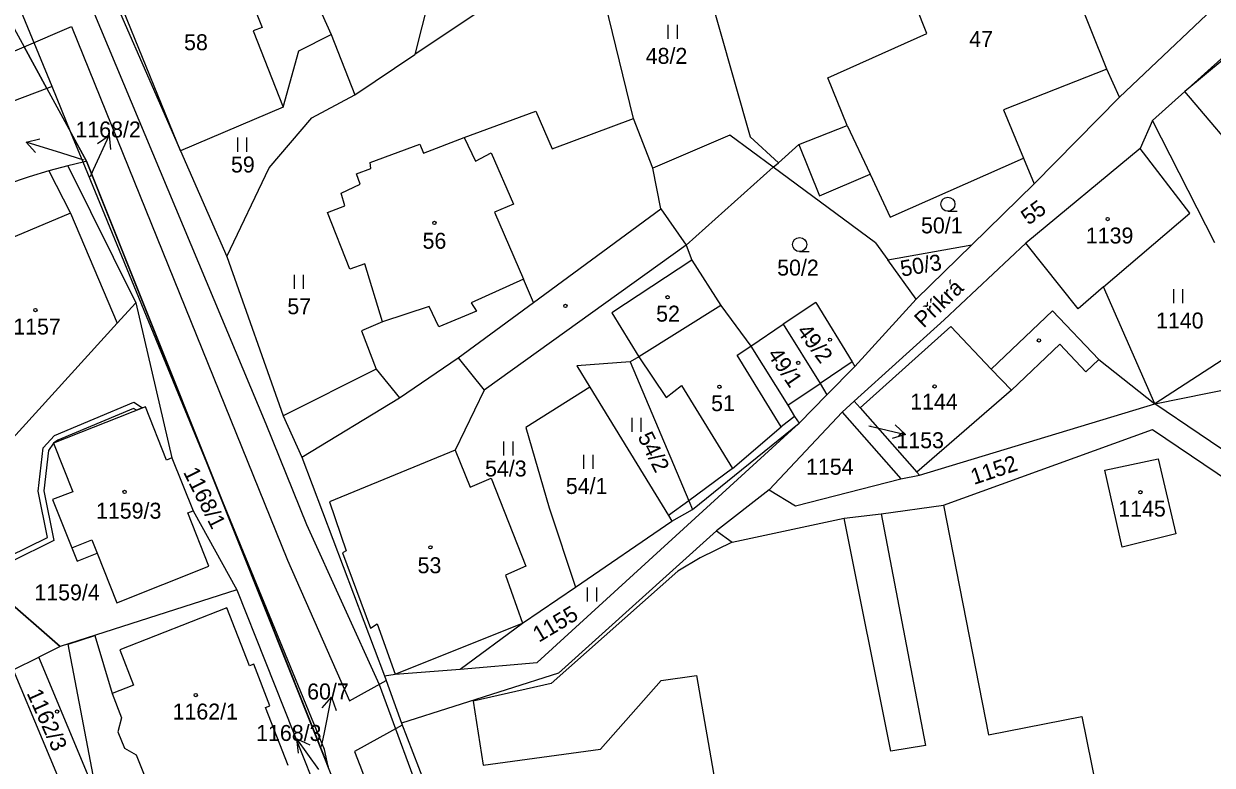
# Model space of a CAD drawing. Extents: x -670359 to -660124, y -978807 to -970072.
# Drawn here: x -670231.4 to -670104.9, y -977870.8 to -977791.9 of the extents above; entities that cross this region are included whole.
import ezdxf

# ---------------------------------------------------------------- set-up
doc = ezdxf.new("R2010")
doc.units = 0
for name, color, linetype in [('Hranice parcel', 7, 'Continuous'), ('Parcelní čísla', 7, 'Continuous'), ('Pop  PČ popisy', 7, 'Continuous'), ('Vnitřní kresba', 7, 'Continuous'), ('Věcná břemena k části', 7, 'Continuous'), ('Značky budov', 7, 'Continuous'), ('Značky kultur', 7, 'Continuous')]:
    doc.layers.add(name, color=color, linetype=linetype)

msp = doc.modelspace()

# ---------------------------------------------------------------- linework, layer by layer
at = {"layer": 'Hranice parcel'}
for points in [[(-670228.39, -977798.54), (-670235.68, -977780.88), (-670248.21, -977752.09), (-670257.66, -977728.06), (-670261.88, -977714.27), (-670262.87, -977707.81), (-670263.3, -977700.83), (-670262.9, -977694.87), (-670261.36, -977686.41), (-670250.36, -977641.2)], [(-670183.39, -977889.81), (-670193.56, -977862.25), (-670201.26, -977845.22), (-670205.62, -977834.5), (-670231.98, -977771.32), (-670242.71, -977745.05), (-670249.53, -977728.04), (-670253.85, -977714.41), (-670254.54, -977710.9), (-670255.07, -977705.75), (-670255.17, -977699.87), (-670254.7, -977694.67), (-670252.82, -977684.15), (-670242.83, -977643.13)], [(-670170.72, -977719.8), (-670189.77, -977795.14)], [(-670116.13, -977796.71), (-670126.35, -977771.21)], [(-670241.06, -977776.57), (-670231.37, -977794.32), (-670228.95, -977798.75), (-670226.38, -977803.45)], [(-670135.31, -977792.9), (-670141.44, -977777.42)], [(-670160.77, -977780.44), (-670154.08, -977803.89)], [(-670224.46, -977783.08), (-670214.71, -977805.39)], [(-670171.73, -977783.05), (-670189.77, -977795.14)], [(-670089.7, -977782.74), (-670107.82, -977799.09)], [(-670166.5, -977801.96), (-670170.62, -977785.06)], [(-670201.68, -977786.36), (-670198.69, -977793.02)], [(-670093.41, -977787.03), (-670107.82, -977799.09)], [(-670114.79, -977799.68), (-670102.21, -977787.73)], [(-670202.14, -977794.75), (-670198.69, -977793.02)], [(-670198.69, -977793.02), (-670196.17, -977799.43)], [(-670145.82, -977797.63), (-670135.31, -977792.9)], [(-670203.78, -977800.74), (-670202.14, -977794.75)], [(-670196.17, -977799.43), (-670189.77, -977795.14)], [(-670114.79, -977799.68), (-670116.13, -977796.71)], [(-670143.78, -977802.68), (-670145.82, -977797.63)], [(-670226.38, -977803.45), (-670228.39, -977798.54)], [(-670200.75, -977801.88), (-670196.17, -977799.43)], [(-670123.86, -977808.92), (-670114.79, -977799.68)], [(-670107.82, -977799.09), (-670111.29, -977802.18)], [(-670203.78, -977800.74), (-670214.71, -977805.39)], [(-670205.27, -977807.21), (-670200.75, -977801.88)], [(-670184.52, -977803.99), (-670176.9, -977801.17)], [(-670176.9, -977801.17), (-670175.17, -977805.18)], [(-670175.17, -977805.18), (-670166.5, -977801.96)], [(-670164.46, -977807.25), (-670166.5, -977801.96)], [(-670111.29, -977802.18), (-670112.59, -977805.14)], [(-670104.66, -977815.19), (-670111.29, -977802.18)], [(-670226.38, -977803.45), (-670224.71, -977806.51)], [(-670225.09, -977806.6), (-670226.38, -977803.45)], [(-670148.92, -977804.72), (-670143.78, -977802.68)], [(-670194.54, -977806.64), (-670189.25, -977804.68)], [(-670189.25, -977804.68), (-670188.86, -977805.64)], [(-670188.86, -977805.64), (-670184.52, -977803.99)], [(-670154.08, -977803.89), (-670151.09, -977806.66)], [(-670148.92, -977804.72), (-670151.09, -977806.66)], [(-670148.92, -977804.72), (-670146.72, -977810.18)], [(-670214.71, -977805.39), (-670209.78, -977816.65)], [(-670112.59, -977805.14), (-670124.75, -977815.21)], [(-670107.3, -977812.02), (-670112.59, -977805.14)], [(-670226.72, -977806.98), (-670228.72, -977807.52)], [(-670225.09, -977806.6), (-670226.72, -977806.98)], [(-670226.72, -977806.98), (-670219.46, -977821.58)], [(-670224.71, -977806.51), (-670225.09, -977806.6)], [(-670211.12, -977840.59), (-670225.09, -977806.6)], [(-670224.71, -977806.51), (-670211.12, -977840.59)], [(-670209.78, -977816.65), (-670205.27, -977807.21)], [(-670195.99, -977807.83), (-670194.47, -977807.28)], [(-670194.47, -977807.28), (-670194.54, -977806.64)], [(-670163.61, -977811.58), (-670164.46, -977807.25)], [(-670160.92, -977815.43), (-670151.63, -977807.14)], [(-670151.63, -977807.14), (-670151.09, -977806.66)], [(-670140.75, -977815.18), (-670151.63, -977807.14)], [(-670139.21, -977812.47), (-670125, -977806.17)], [(-670125, -977806.17), (-670123.86, -977808.92)], [(-670230.81, -977808.15), (-670240.51, -977811.44)], [(-670228.72, -977807.52), (-670230.81, -977808.15)], [(-670228.72, -977807.52), (-670226.43, -977812.02)], [(-670195.6, -977808.95), (-670195.99, -977807.83)], [(-670146.72, -977810.18), (-670141.34, -977807.89)], [(-670141.34, -977807.89), (-670139.21, -977812.47)], [(-670197.61, -977809.9), (-670195.6, -977808.95)], [(-670123.86, -977808.92), (-670130.5, -977815.4)], [(-670197.22, -977811.26), (-670197.61, -977809.9)], [(-670226.43, -977812.02), (-670240, -977817.76)], [(-670199.06, -977811.97), (-670197.22, -977811.26)], [(-670196.71, -977817.98), (-670199.06, -977811.97)], [(-670177.17, -977821.54), (-670163.61, -977811.58)], [(-670163.61, -977811.58), (-670160.92, -977815.43)], [(-670116.48, -977819.88), (-670107.3, -977812.02)], [(-670160.92, -977815.43), (-670182.39, -977830.88)], [(-670160.92, -977815.43), (-670160.29, -977817.04)], [(-670140.75, -977815.18), (-670139.43, -977817.01)], [(-670139.43, -977817.01), (-670130.5, -977815.4)], [(-670136.43, -977821.2), (-670130.5, -977815.4)], [(-670124.75, -977815.21), (-670133.45, -977823.38)], [(-670119.19, -977822.2), (-670124.75, -977815.21)], [(-670209.78, -977816.65), (-670203.78, -977833.61)], [(-670195.1, -977817.44), (-670196.71, -977817.98)], [(-670193.23, -977823.61), (-670195.1, -977817.44)], [(-670160.29, -977817.04), (-670168.81, -977822.66)], [(-670160.29, -977817.04), (-670157.2, -977821.86)], [(-670136.43, -977821.2), (-670139.43, -977817.01)], [(-670178.23, -977819.07), (-670183.77, -977821.59)], [(-670177.17, -977821.54), (-670178.23, -977819.07)], [(-670116.48, -977819.88), (-670119.19, -977822.2)], [(-670111.02, -977832.34), (-670116.48, -977819.88)], [(-670142.95, -977828.35), (-670136.43, -977821.2)], [(-670219.46, -977821.58), (-670221.47, -977823.73)], [(-670219.46, -977821.58), (-670215.65, -977838.09)], [(-670188.25, -977821.96), (-670193.23, -977823.61)], [(-670187.23, -977824.13), (-670188.25, -977821.96)], [(-670183.21, -977822.48), (-670187.23, -977824.13)], [(-670185.17, -977827.42), (-670177.17, -977821.54)], [(-670183.77, -977821.59), (-670183.21, -977822.48)], [(-670157.2, -977821.86), (-670165.96, -977827.32)], [(-670157.2, -977821.86), (-670154.03, -977826.2)], [(-670147.12, -977821.53), (-670150.58, -977823.86)], [(-670147.12, -977821.53), (-670143.24, -977827.87)], [(-670221.47, -977823.73), (-670235.03, -977838.67)], [(-670168.81, -977822.66), (-670165.96, -977827.32)], [(-670133.45, -977823.38), (-670143.02, -977832.05)], [(-670154.03, -977826.2), (-670150.58, -977823.86)], [(-670150.58, -977823.86), (-670146.66, -977830.17)], [(-670154.03, -977826.2), (-670150.08, -977832.47)], [(-670099.93, -977825.14), (-670111.02, -977832.34)], [(-670191.4, -977831.7), (-670185.17, -977827.42)], [(-670165.96, -977827.32), (-670166.85, -977827.87)], [(-670166.85, -977827.87), (-670172.55, -977828.3)], [(-670172.55, -977828.3), (-670171.16, -977830.57)], [(-670166.85, -977827.87), (-670160.63, -977842.65)], [(-670142.95, -977828.35), (-670145.92, -977831.37)], [(-670143.24, -977827.87), (-670142.95, -977828.35)], [(-670111.02, -977832.34), (-670099.64, -977830.02)], [(-670182.39, -977830.88), (-670185.48, -977837.26)], [(-670171.16, -977830.57), (-670177.98, -977834.86)], [(-670171.16, -977830.57), (-670162.79, -977844.24)], [(-670146.66, -977830.17), (-670145.92, -977831.37)], [(-670201.81, -977838.02), (-670191.4, -977831.7)], [(-670150.08, -977832.47), (-670149.36, -977833.67)], [(-670148.89, -977834.39), (-670145.92, -977831.37)], [(-670143.02, -977832.05), (-670144.32, -977833.23)], [(-670143.02, -977832.05), (-670142.4, -977832.76)], [(-670136.08, -977839.92), (-670111.02, -977832.34)], [(-670087.45, -977848.3), (-670111.02, -977832.34)], [(-670218.46, -977832.65), (-670228.24, -977836.52)], [(-670216.21, -977838.32), (-670218.46, -977832.65)], [(-670203.78, -977833.61), (-670201.81, -977838.02)], [(-670144.32, -977833.23), (-670152.06, -977841.49)], [(-670149.36, -977833.67), (-670148.89, -977834.39)], [(-670144.32, -977833.23), (-670138.05, -977840.31)], [(-670142.4, -977832.76), (-670136.36, -977839.6)], [(-670177.98, -977834.86), (-670175.47, -977843.4), (-670172.69, -977851.85)], [(-670176.76, -977859.87), (-670148.89, -977834.39)], [(-670160.24, -977843.59), (-670148.89, -977834.39)], [(-670133.51, -977843.14), (-670111.28, -977835.06)], [(-670111.28, -977835.06), (-670086.58, -977851.74)], [(-670228.24, -977836.52), (-670226.19, -977841.7)], [(-670185.48, -977837.26), (-670183.91, -977841.19)], [(-670215.65, -977838.09), (-670216.21, -977838.32)], [(-670215.65, -977838.09), (-670213.37, -977843.72)], [(-670201.81, -977838.02), (-670193.02, -977861.28)], [(-670116.35, -977839.38), (-670110.67, -977838.18)], [(-670110.67, -977838.18), (-670108.8, -977846.19)], [(-670138.05, -977840.31), (-670136.08, -977839.92)], [(-670136.36, -977839.6), (-670136.08, -977839.92)], [(-670114.49, -977847.59), (-670116.35, -977839.38)], [(-670199.01, -977870.96), (-670199.39, -977869.14), (-670211.12, -977840.59)], [(-670211.12, -977840.59), (-670199.01, -977870.96)], [(-670183.91, -977841.19), (-670181.66, -977840.24)], [(-670181.66, -977840.24), (-670177.97, -977849.63)], [(-670149.27, -977843.19), (-670138.05, -977840.31)], [(-670226.19, -977841.7), (-670228.33, -977842.51)], [(-670228.33, -977842.51), (-670226.3, -977847.66)], [(-670160.63, -977842.65), (-670160.24, -977843.59)], [(-670152.06, -977841.49), (-670157.69, -977845.85)], [(-670152.06, -977841.49), (-670149.27, -977843.19)], [(-670213.94, -977843.94), (-670213.37, -977843.72)], [(-670211.69, -977849.63), (-670213.94, -977843.94)], [(-670213.37, -977843.72), (-670208.71, -977852.13)], [(-670162.42, -977844.84), (-670160.24, -977843.59)], [(-670140.16, -977844.05), (-670133.51, -977843.14)], [(-670133.51, -977843.14), (-670128.72, -977867.57)], [(-670172.69, -977851.85), (-670162.42, -977844.84)], [(-670162.79, -977844.24), (-670162.42, -977844.84)], [(-670156.02, -977847.06), (-670144.08, -977844.5)], [(-670144.08, -977844.5), (-670140.16, -977844.05)], [(-670157.69, -977845.85), (-670174.49, -977861)], [(-670157.69, -977845.85), (-670156.02, -977847.06)], [(-670108.8, -977846.19), (-670114.49, -977847.59)], [(-670226.3, -977847.66), (-670225.73, -977849.08)], [(-670225.73, -977849.08), (-670223.6, -977848.23)], [(-670223.6, -977848.23), (-670221.5, -977853.52)], [(-670221.5, -977853.52), (-670211.69, -977849.63)], [(-670177.97, -977849.63), (-670180.14, -977850.57)], [(-670180.14, -977850.57), (-670178.33, -977855.7)], [(-670234.05, -977852.48), (-670227.51, -977858.17)], [(-670208.71, -977852.13), (-670227.51, -977858.17)], [(-670208.71, -977852.13), (-670199.68, -977874.91)], [(-670178.33, -977855.7), (-670172.69, -977851.85)], [(-670209.8, -977854.06), (-670221.19, -977858.51)], [(-670207.39, -977860.24), (-670209.8, -977854.06)], [(-670184.95, -977860.58), (-670178.33, -977855.7)], [(-670227.51, -977858.17), (-670229.81, -977859.3)], [(-670221.19, -977858.51), (-670219.71, -977862.3)], [(-670232.52, -977860.64), (-670229.81, -977859.3)], [(-670223.55, -977874.27), (-670229.81, -977859.3)], [(-670206.92, -977860.06), (-670207.39, -977860.24)], [(-670205.23, -977864.49), (-670206.92, -977860.06)], [(-670184.95, -977860.58), (-670176.76, -977859.87)], [(-670232.52, -977860.64), (-670226.34, -977875.43)], [(-670193.02, -977861.28), (-670191.89, -977861.13)], [(-670193.02, -977861.28), (-670191.21, -977866.33)], [(-670191.89, -977861.13), (-670184.95, -977860.58)], [(-670174.49, -977861), (-670191.21, -977866.33)], [(-670219.71, -977862.3), (-670221.99, -977863.19)], [(-670221.99, -977863.19), (-670220.99, -977865.75)], [(-670205.66, -977864.66), (-670205.23, -977864.49)], [(-670203.25, -977870.84), (-670205.66, -977864.66)], [(-670220.99, -977865.75), (-670221.4, -977867.26)], [(-670191.21, -977866.33), (-670188.19, -977874.13)], [(-670128.72, -977867.57), (-670118.79, -977865.64)], [(-670118.79, -977865.64), (-670116.23, -977878.21)], [(-670221.4, -977867.26), (-670220.69, -977869.01)], [(-670220.69, -977869.01), (-670219.45, -977869.7)], [(-670219.45, -977869.7), (-670218.37, -977872.37)]]:
    msp.add_lwpolyline(points, dxfattribs=at)
at = {"layer": 'Parcelní čísla'}
for p, q in [((-670230.14, -977805.56), (-670231.16, -977804.46)), ((-670223.54, -977804.62), (-670222.32, -977803.75)), ((-670225, -977806.38), (-670227.34, -977805.65)), ((-670224.31, -977808.13), (-670223.97, -977807.39)), ((-670138.65, -977834.56), (-670137.56, -977835.6)), ((-670199.64, -977864.7), (-670198.65, -977863.57)), ((-670202.18, -977869.52), (-670202.34, -977868.02)), ((-670199.7, -977868.81), (-670199.43, -977867.49))]:
    msp.add_line(p, q, dxfattribs=at)
for points in [[(-670227.34, -977805.65), (-670231.16, -977804.46), (-670229.7, -977804.13)], [(-670223.97, -977807.39), (-670222.32, -977803.75), (-670222.17, -977805.24)], [(-670141.45, -977834.66), (-670137.56, -977835.6), (-670139, -977836.02)], [(-670199.43, -977867.49), (-670198.65, -977863.57), (-670198.17, -977864.99)], [(-670199.99, -977871.26), (-670202.34, -977868.02), (-670200.97, -977868.64)]]:
    msp.add_lwpolyline(points, dxfattribs=at)
at = {"layer": 'Vnitřní kresba'}
for points in [[(-670214.71, -977805.39), (-670222.8, -977785.49)], [(-670207.93, -977787.43), (-670206.04, -977792.25)], [(-670206.04, -977792.25), (-670206.98, -977792.62)], [(-670206.98, -977792.62), (-670203.78, -977800.74)], [(-670116.13, -977796.71), (-670127.12, -977801.03)], [(-670100.84, -977807.3), (-670107.82, -977799.09)], [(-670127.12, -977801.03), (-670125, -977806.17)], [(-670143.78, -977802.68), (-670141.34, -977807.89)], [(-670184.52, -977803.99), (-670183.34, -977806.48)], [(-670156.27, -977803.71), (-670164.46, -977807.25)], [(-670151.63, -977807.14), (-670156.27, -977803.71)], [(-670183.34, -977806.48), (-670181.65, -977805.61)], [(-670181.65, -977805.61), (-670179.29, -977811.07)], [(-670179.29, -977811.07), (-670181.3, -977811.93)], [(-670226.43, -977812.02), (-670221.47, -977823.73)], [(-670181.3, -977811.93), (-670178.23, -977819.07)], [(-670128.43, -977828.63), (-670121.91, -977822.42)], [(-670121.91, -977822.42), (-670116.98, -977827.6)], [(-670193.23, -977823.61), (-670195.47, -977824.55)], [(-670195.47, -977824.55), (-670193.9, -977828.64)], [(-670142.4, -977832.76), (-670132.73, -977824.11)], [(-670132.73, -977824.11), (-670128.43, -977828.63)], [(-670155.48, -977827.15), (-670154.03, -977826.2)], [(-670121.15, -977825.97), (-670126.3, -977830.87)], [(-670118.36, -977828.91), (-670121.15, -977825.97)], [(-670185.17, -977827.42), (-670182.39, -977830.88)], [(-670165.96, -977827.32), (-670163.03, -977831.66)], [(-670150.81, -977834.78), (-670155.48, -977827.15)], [(-670193.9, -977828.64), (-670203.78, -977833.61)], [(-670193.9, -977828.64), (-670191.4, -977831.7)], [(-670143.24, -977827.87), (-670146.66, -977830.17)], [(-670128.43, -977828.63), (-670126.3, -977830.87)], [(-670116.98, -977827.6), (-670118.36, -977828.91)], [(-670116.98, -977827.6), (-670111.02, -977832.34)], [(-670163.03, -977831.66), (-670161.42, -977830.39)], [(-670161.42, -977830.39), (-670155.97, -977839.22)], [(-670150.08, -977832.47), (-670146.66, -977830.17)], [(-670126.3, -977830.87), (-670136.36, -977839.6)], [(-670149.36, -977833.67), (-670150.81, -977834.78)], [(-670155.97, -977839.22), (-670150.81, -977834.78)], [(-670185.48, -977837.26), (-670198.88, -977842.76)], [(-670155.97, -977839.22), (-670160.63, -977842.65)], [(-670160.63, -977842.65), (-670162.79, -977844.24)], [(-670198.88, -977842.76), (-670197.08, -977847.97)], [(-670139.14, -977869.33), (-670144.08, -977844.5)], [(-670140.16, -977844.05), (-670135.45, -977868.72)], [(-670226.3, -977847.66), (-670224.16, -977846.81)], [(-670224.16, -977846.81), (-670223.6, -977848.23)], [(-670156.02, -977847.06), (-670159.4, -977848.72)], [(-670197.08, -977847.97), (-670197.48, -977848.21)], [(-670197.48, -977848.21), (-670194.5, -977856.23)], [(-670159.4, -977848.72), (-670161.81, -977850.14)], [(-670161.81, -977850.14), (-670175.26, -977862.12)], [(-670194.5, -977856.23), (-670193.78, -977855.75)], [(-670193.78, -977855.75), (-670191.89, -977861.13)], [(-670191.89, -977861.13), (-670178.33, -977855.7)], [(-670163.57, -977861.8), (-670159.81, -977861.27)], [(-670159.81, -977861.27), (-670157.73, -977873.28)], [(-670175.26, -977862.12), (-670183.59, -977863.98)], [(-670170.03, -977869.12), (-670163.57, -977861.8)], [(-670183.59, -977863.98), (-670182.52, -977870.79)], [(-670182.52, -977870.79), (-670170.03, -977869.12)], [(-670135.45, -977868.72), (-670139.14, -977869.33)]]:
    msp.add_lwpolyline(points, dxfattribs=at)
at = {"layer": 'Věcná břemena k části'}
for points in [[(-670231.37, -977794.32), (-670226.31, -977792.17), (-670203.33, -977848.99), (-670196.72, -977863.94), (-670192.84, -977861.8), (-670191.21, -977866.33), (-670191.12, -977866.56), (-670196.22, -977869.36), (-670195.63, -977870.79), (-670152.49, -977985.64), (-670151.43, -977993.09), (-670152.31, -978015.47), (-670159.21, -978043.03)], [(-670257.67, -977808.33), (-670256.79, -977805.13), (-670231.37, -977794.32)], [(-670231.37, -977794.32), (-670228.95, -977798.75), (-670250.62, -977806.97)], [(-670228.39, -977798.54), (-670228.95, -977798.75), (-670231.37, -977794.32)], [(-670226.38, -977803.45), (-670228.39, -977798.54)], [(-670159.21, -978043.03), (-670166.44, -978073.84), (-670169.93, -978096.39), (-670171.6, -978117.05), (-670173.62, -978117.69), (-670174.87, -978118.08), (-670174.67, -978116.45), (-670172.91, -978096.03), (-670169.38, -978073.26), (-670162.13, -978042.33), (-670155.29, -978015.05), (-670154.43, -977993.25), (-670155.41, -977986.38), (-670176.81, -977929.42), (-670177.71, -977925.53), (-670186.89, -977901.98), (-670197.75, -977874.12), (-670224.71, -977806.51), (-670226.38, -977803.45)], [(-670235.03, -977838.67), (-670221.47, -977823.73), (-670219.46, -977821.58), (-670215.65, -977838.09), (-670216.21, -977838.32), (-670218.46, -977832.65), (-670228.24, -977836.52), (-670226.19, -977841.7), (-670228.33, -977842.51), (-670226.3, -977847.66), (-670225.73, -977849.08), (-670223.6, -977848.23), (-670221.5, -977853.52), (-670211.69, -977849.63), (-670213.94, -977843.94), (-670213.37, -977843.72), (-670208.71, -977852.13), (-670227.51, -977858.17), (-670234.05, -977852.48)], [(-670233, -977848.58), (-670228.87, -977846.55), (-670229.87, -977841.62), (-670229.33, -977837.03), (-670228.12, -977835.71), (-670219.67, -977832.15), (-670218.76, -977832.77)], [(-670218.76, -977832.77), (-670219.39, -977833.02), (-670219.74, -977832.83), (-670227.77, -977836.21), (-670228.24, -977836.52), (-670228.76, -977837.29), (-670229.26, -977841.59), (-670228.19, -977846.88), (-670232.77, -977849.14)], [(-670226.69, -977857.91), (-670223.83, -977856.99), (-670221.99, -977863.19), (-670220.99, -977865.75), (-670221.4, -977867.26), (-670220.69, -977869.01), (-670219.45, -977869.7), (-670218.37, -977872.37), (-670219.76, -977872.93), (-670218.52, -977879.98), (-670219.34, -977884.64), (-670222.56, -977885.63), (-670221.48, -977879.46), (-670223.55, -977874.27), (-670226.69, -977857.91)]]:
    msp.add_lwpolyline(points, dxfattribs=at)
at = {"layer": 'Značky budov'}
for centre in [(-670187.7, -977813.07), (-670116.05, -977812.66), (-670162.89, -977820.98), (-670230.16, -977822.35), (-670145.6, -977825.5), (-670148.98, -977827.97), (-670157.36, -977830.51), (-670134.47, -977830.48), (-670220.67, -977841.71), (-670112.56, -977841.74), (-670188.12, -977847.61), (-670213.09, -977863.34), (-670227.86, -977865.1)]:
    msp.add_circle(centre, 0.175, dxfattribs=at)
at = {"layer": 'Značky kultur'}
for p, q in [((-670162.84, -977791.96), (-670162.84, -977793.46)), ((-670161.84, -977793.46), (-670161.84, -977791.96)), ((-670208.67, -977803.99), (-670208.67, -977805.49)), ((-670207.67, -977805.49), (-670207.67, -977803.99)), ((-670133.05, -977811.83), (-670132.05, -977811.83)), ((-670148.83, -977816.12), (-670147.83, -977816.12)), ((-670202.64, -977818.59), (-670202.64, -977820.09)), ((-670201.64, -977820.09), (-670201.64, -977818.59)), ((-670109.04, -977820.11), (-670109.04, -977821.61)), ((-670108.04, -977821.61), (-670108.04, -977820.11)), ((-670166.7, -977833.81), (-670166.7, -977835.31)), ((-670165.7, -977835.31), (-670165.7, -977833.81)), ((-670180.33, -977836.34), (-670180.33, -977837.84)), ((-670179.33, -977837.84), (-670179.33, -977836.34)), ((-670171.82, -977837.77), (-670171.82, -977839.27)), ((-670170.82, -977839.27), (-670170.82, -977837.77)), ((-670171.43, -977851.88), (-670171.43, -977853.38)), ((-670170.43, -977853.38), (-670170.43, -977851.88))]:
    msp.add_line(p, q, dxfattribs=at)
for centre, radius in [((-670133.05, -977811.08), 0.75), ((-670187.7, -977813.07), 0.175), ((-670116.05, -977812.66), 0.175), ((-670148.83, -977815.37), 0.75), ((-670162.89, -977820.98), 0.175), ((-670230.16, -977822.35), 0.175), ((-670173.75, -977821.91), 0.175), ((-670145.6, -977825.5), 0.175), ((-670123.37, -977825.58), 0.175), ((-670148.98, -977827.97), 0.175), ((-670157.36, -977830.51), 0.175), ((-670134.47, -977830.48), 0.175), ((-670220.67, -977841.71), 0.175), ((-670112.56, -977841.74), 0.175), ((-670188.12, -977847.61), 0.175), ((-670213.09, -977863.34), 0.175), ((-670227.86, -977865.1), 0.175)]:
    msp.add_circle(centre, radius, dxfattribs=at)

# ---------------------------------------------------------------- texts
at = {"layer": 'Parcelní čísla'}
for s, height, p in [('58', 1.7, (-670214.34, -977794.68)), ('47', 1.7, (-670130.78, -977794.33)), ('48/2', 1.7, (-670165.21, -977796.13)), ('1168/2', 1.7, (-670225.9, -977803.97)), ('59', 1.7, (-670209.35, -977807.7)), ('61/6', 0.1, (-670225.15, -977806.38)), ('1168/2', 0.1, (-670224.54, -977808.13)), ('50/1', 1.7, (-670135.91, -977814.18)), ('1139', 1.7, (-670118.37, -977815.26)), ('56', 1.7, (-670188.96, -977815.82)), ('50/2', 1.7, (-670151.22, -977818.68)), ('57', 1.7, (-670203.35, -977822.79)), ('52', 1.7, (-670164.1, -977823.58)), ('1157', 1.7, (-670232.52, -977824.95)), ('1140', 1.7, (-670110.9, -977824.31)), ('1144', 1.7, (-670137.06, -977832.94)), ('51', 1.7, (-670158.25, -977833.11)), ('1153', 0.1, (-670141.45, -977834.66)), ('1153', 1.7, (-670138.53, -977837.06)), ('54/3', 1.7, (-670182.31, -977840.07)), ('1154', 1.7, (-670148.15, -977839.88)), ('54/1', 1.7, (-670173.71, -977841.93)), ('1145', 1.7, (-670114.92, -977844.34)), ('1159/3', 1.7, (-670223.71, -977844.56)), ('53', 1.7, (-670189.49, -977850.37)), ('1159/4', 1.7, (-670230.27, -977853.26)), ('60/7', 1.7, (-670201.24, -977863.81)), ('1162/1', 1.7, (-670215.56, -977865.95)), ('1168/3', 1.7, (-670206.67, -977868.23)), ('60/7', 0.1, (-670199.86, -977868.81))]:
    msp.add_text(s, height=height, dxfattribs=at).set_placement(p)
for s, rotation, p in [('55', 36.1796, (-670124.48, -977813.37)), ('50/3', 9.9274, (-670137.96, -977818.8)), ('49/2', 306.5911, (-670149.2, -977824.62)), ('49/1', 304.1436, (-670152.32, -977827.08)), ('54/2', 296.563, (-670166.11, -977835.84)), ('1152', 18.435, (-670130.29, -977840.97)), ('1168/1', 296.5651, (-670214.46, -977839.6)), ('1155', 30.8609, (-670176.58, -977857.78)), ('1162/3', 294.2744, (-670231.12, -977863.14))]:
    msp.add_text(s, height=1.7, rotation=rotation, dxfattribs=at).set_placement(p)
at = {"layer": 'Pop  PČ popisy'}
msp.add_text('Příkrá', height=1.7, rotation=43.8018, dxfattribs=at).set_placement((-670135.63, -977824.34))

doc.saveas('drawing.dxf')
